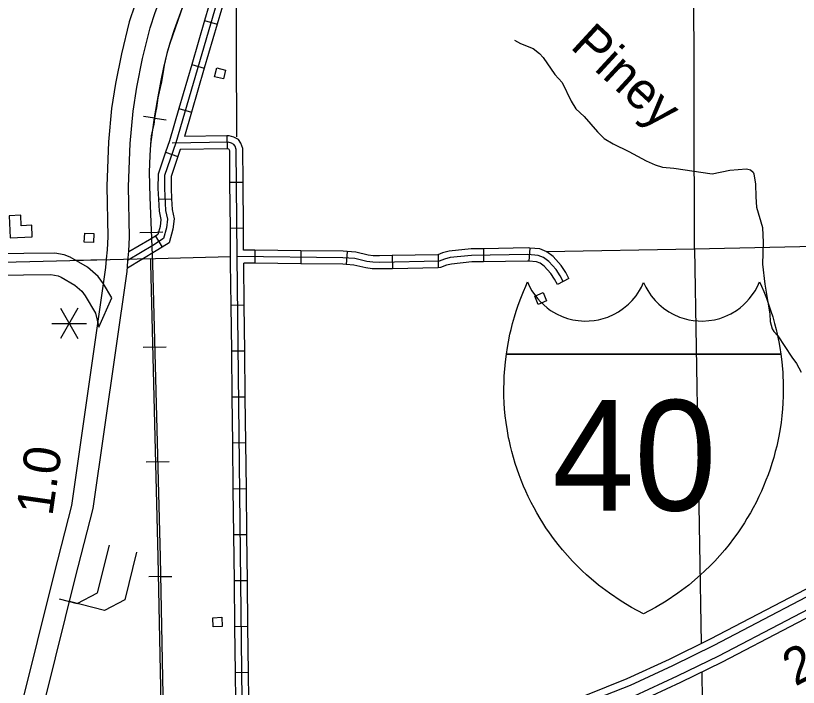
# Model space of a CAD drawing. Extents: x 1084508 to 1142749, y 1057638 to 1093403.
# Drawn here: x 1101971 to 1104795, y 1077367 to 1079791 of the extents above; entities that cross this region are included whole.
import ezdxf

# ---------------------------------------------------------------- set-up
doc = ezdxf.new("R2010")
doc.units = 0
for name, color, linetype in [('Level 10', 7, 'Continuous'), ('Level 15', 7, 'Continuous'), ('Level 19', 7, 'Continuous'), ('Level 23', 7, 'Continuous'), ('Level 31', 7, 'Continuous'), ('Level 32', 7, 'Continuous'), ('Level 33', 7, 'Continuous'), ('Level 35', 7, 'Continuous'), ('Level 40', 7, 'Continuous'), ('Level 48', 7, 'Continuous'), ('Level 5', 7, 'Continuous'), ('Level 56', 7, 'Continuous'), ('Level 58', 7, 'Continuous'), ('Level 6', 7, 'Continuous')]:
    doc.layers.add(name, color=color, linetype=linetype)

msp = doc.modelspace()

# ---------------------------------------------------------------- linework, layer by layer
at = {"layer": 'Level 10'}
msp.add_line((1102270.9, 1078666.9), (1102318, 1078772.6), dxfattribs=at)
for points in [[(1102112.4, 1078934.1), (1101108.6, 1078923.4), (1100079.5, 1078908)], [(1102318, 1078772.6), (1102287.3, 1078823.3), (1102268.6, 1078850.4), (1102230.2, 1078883.4), (1102167.9, 1078919.3), (1102145.2, 1078927.7), (1102112.4, 1078934.1)], [(1100079.8, 1078829.5), (1101109.7, 1078845), (1102097.5, 1078857.1)], [(1102097.5, 1078857.1), (1102123.9, 1078851.9), (1102134.4, 1078848), (1102184.6, 1078819.1), (1102209.7, 1078797.5), (1102221.4, 1078780.6), (1102259.3, 1078718.1), (1102270.9, 1078666.9)]]:
    msp.add_lwpolyline(points, dxfattribs=at)
at = {"layer": 'Level 15'}
for points in [[(1102601.4, 1080345.6), (1102466.9, 1080003.8), (1102400.3, 1079828.9), (1102380.8, 1079769.2), (1102352.2, 1079653.7), (1102330.4, 1079546.7), (1102316.8, 1079455.7), (1102305.9, 1079335.4), (1102299.9, 1079175.8), (1102303.2, 1078993.1), (1102301.2, 1078946.7), (1102297.8, 1078912.2), (1102295.4, 1078882)], [(1102372.7, 1078868.2), (1102376, 1078904.9), (1102379.5, 1078941.3), (1102381.7, 1078992.1), (1102378.4, 1079175.1), (1102384.2, 1079330.4), (1102394.7, 1079446.4), (1102407.7, 1079533.1), (1102428.7, 1079636.5), (1102456.3, 1079747.5), (1102474.3, 1079802.7), (1102540.1, 1079975.5), (1102673.6, 1080315)], [(1102295.4, 1078882), (1102172.2, 1078023.5)], [(1102250.3, 1078012.2), (1102372.7, 1078868.2)], [(1102172.2, 1078023.5), (1102109.9, 1077779.1), (1101926.1, 1077039.1)], [(1102008.9, 1077046.6), (1102186, 1077760), (1102250.3, 1078012.2)]]:
    msp.add_lwpolyline(points, dxfattribs=at)
at = {"layer": 'Level 19'}
for points in [[(1102041.9, 1077000.5), (1102364, 1077029.2), (1102895.3, 1077072.8), (1103063.6, 1077095.3), (1103199.5, 1077115.4), (1103324.5, 1077139.6), (1103502.7, 1077178.6), (1103618.3, 1077206.1), (1103787.8, 1077254.8), (1103877.7, 1077284.5), (1104027.7, 1077339.3), (1104176.7, 1077398.9), (1104329.2, 1077469.3), (1104477.2, 1077541.6), (1104964.7, 1077796.3), (1105121.2, 1077875.3), (1105222.4, 1077921.4), (1105310.5, 1077958), (1105422.2, 1078000.9), (1105533.8, 1078039.7), (1105697.7, 1078089.4), (1105898.8, 1078144), (1106079.8, 1078187.8)], [(1106080.5, 1078160.5), (1105905.5, 1078118.2), (1105705, 1078063.7), (1105542, 1078014.4), (1105431.3, 1077975.8), (1105320.4, 1077933.2), (1105233, 1077897), (1105132.8, 1077851.2), (1104976.9, 1077772.6), (1104489.2, 1077517.7), (1104340.7, 1077445.2), (1104187.3, 1077374.3), (1104037.2, 1077314.4), (1103886.5, 1077259.3), (1103795.7, 1077229.3), (1103625.1, 1077180.3), (1103508.6, 1077152.6), (1103329.9, 1077113.5), (1103204, 1077089.1), (1103067.3, 1077068.8), (1102898.2, 1077046.2), (1102366.3, 1077002.6), (1102029.6, 1076972.6)], [(1102029, 1076931.6), (1102370.2, 1076962), (1102902.9, 1077005.6), (1103073.4, 1077028.4), (1103211.2, 1077048.8), (1103338.5, 1077073.5), (1103518.1, 1077112.8), (1103635.8, 1077140.8), (1103808.1, 1077190.3), (1103900.2, 1077220.8), (1104052.2, 1077276.3), (1104203.8, 1077336.8), (1104358.6, 1077408.3), (1104508, 1077481.3), (1104995.9, 1077736.3), (1105150.8, 1077814.5), (1105249.7, 1077859.5), (1105335.9, 1077895.3), (1105445.7, 1077937.5), (1105555, 1077975.6), (1105716.7, 1078024.5), (1105916, 1078078.6), (1106081.9, 1078118.8)], [(1106082.7, 1078091.5), (1105922.6, 1078052.8), (1105724, 1077998.8), (1105563.3, 1077950.2), (1105454.9, 1077912.4), (1105345.8, 1077870.5), (1105260.3, 1077835.1), (1105162.3, 1077790.4), (1105008.1, 1077712.5), (1104520, 1077457.5), (1104370, 1077384.2), (1104214.3, 1077312.3), (1104061.7, 1077251.3), (1103909, 1077195.6), (1103816, 1077164.8), (1103642.6, 1077115), (1103524.1, 1077086.8), (1103343.9, 1077047.4), (1103215.7, 1077022.5), (1103077.1, 1077002), (1102905.8, 1076979.1), (1102372.4, 1076935.4), (1102017, 1076903.7)]]:
    msp.add_lwpolyline(points, dxfattribs=at)
at = {"layer": 'Level 23'}
for points in [[(1103741.3, 1078569.7), (1103744.9, 1078593.4), (1103748.7, 1078614.3), (1103754.2, 1078641.3), (1103758.3, 1078658.9), (1103763.6, 1078679.7), (1103770.5, 1078704.3), (1103776.8, 1078724.8), (1103783.9, 1078745.9), (1103793.3, 1078771.9), (1103803, 1078796.2), (1103811.1, 1078815.2), (1103817.8, 1078830.1), (1103825.1, 1078814), (1103833.6, 1078798.7), (1103842.8, 1078784.6), (1103854.8, 1078769), (1103864.4, 1078758.5), (1103876.1, 1078747.1), (1103888, 1078737.1), (1103901, 1078727.7), (1103921.5, 1078715.4), (1103942.6, 1078705.6), (1103961.6, 1078698.9), (1103980.5, 1078694), (1104000.7, 1078690.7), (1104024.2, 1078689.1), (1104039.7, 1078689.4), (1104057.4, 1078691.1), (1104073.2, 1078693.8), (1104090.1, 1078697.9), (1104107.1, 1078703.6), (1104130, 1078713.7), (1104145.8, 1078722.5), (1104164.2, 1078735.1), (1104181.8, 1078749.9), (1104194.6, 1078762.8), (1104209.3, 1078780.7), (1104221.4, 1078798.8), (1104228.5, 1078811.5), (1104236.3, 1078828.2)], [(1104236.3, 1078828.2), (1104244.1, 1078811.5), (1104251.2, 1078798.8), (1104263.3, 1078780.7), (1104278, 1078762.8), (1104290.8, 1078749.9), (1104308.4, 1078735.1), (1104326.8, 1078722.5), (1104342.6, 1078713.7), (1104365.5, 1078703.6), (1104382.5, 1078697.9), (1104399.4, 1078693.8), (1104415.2, 1078691.1), (1104432.9, 1078689.4), (1104448.4, 1078689.1), (1104471.9, 1078690.7), (1104492.1, 1078694), (1104510.9, 1078698.9), (1104530, 1078705.6), (1104551.1, 1078715.4), (1104571.6, 1078727.7), (1104584.6, 1078737.1), (1104596.5, 1078747.1), (1104608.2, 1078758.5), (1104617.7, 1078769), (1104629.8, 1078784.6), (1104639, 1078798.7), (1104647.5, 1078814), (1104654.8, 1078830.1), (1104661.5, 1078815.2), (1104669.6, 1078796.2), (1104679.3, 1078771.9), (1104688.7, 1078745.9), (1104695.8, 1078724.8), (1104702.1, 1078704.3), (1104709, 1078679.7), (1104714.3, 1078658.9), (1104718.4, 1078641.3), (1104723.9, 1078614.3), (1104727.7, 1078593.4), (1104731.3, 1078569.7)], [(1104236.3, 1077631.9), (1104192.9, 1077655.1), (1104154.8, 1077678), (1104112.8, 1077706.4), (1104073.6, 1077736.1), (1104030.7, 1077772.6), (1104014.8, 1077787.5), (1103996.6, 1077805.3), (1103979.7, 1077822.7), (1103961.3, 1077842.9), (1103943.2, 1077863.9), (1103928.1, 1077882.6), (1103911.7, 1077903.9), (1103896.8, 1077924.5), (1103883.9, 1077943.4), (1103872.6, 1077960.9), (1103863.2, 1077976), (1103850.8, 1077997.1), (1103841.2, 1078014.4), (1103830.6, 1078034.6), (1103820.3, 1078055.6), (1103811.4, 1078074.9), (1103803.2, 1078093.6), (1103794.7, 1078114.6), (1103787.3, 1078134), (1103780.1, 1078154.3), (1103773.2, 1078175.5), (1103766.7, 1078197.2), (1103761, 1078217.9), (1103756.1, 1078237.6), (1103752.1, 1078255.1), (1103749.4, 1078268.1), (1103744.7, 1078293.3), (1103740.1, 1078322.4), (1103737.1, 1078346.7), (1103734.8, 1078372.2), (1103733.5, 1078392.9), (1103732.6, 1078419.1), (1103732.3, 1078443.6), (1103732.8, 1078470.8), (1103733.5, 1078488.8), (1103734.6, 1078505.2), (1103735.3, 1078515.6), (1103737.9, 1078542.3), (1103741.3, 1078569.7)], [(1104731.3, 1078569.7), (1103741.3, 1078569.7)], [(1103741.3, 1078569.7), (1104731.3, 1078569.7)], [(1104731.3, 1078569.7), (1104734.7, 1078542.3), (1104737.3, 1078515.6), (1104738.1, 1078505.2), (1104739, 1078488.8), (1104739.8, 1078470.8), (1104740.3, 1078443.6), (1104740, 1078419.1), (1104739.1, 1078392.9), (1104737.8, 1078372.2), (1104735.5, 1078346.7), (1104732.5, 1078322.4), (1104727.9, 1078293.3), (1104723.2, 1078268.1), (1104720.5, 1078255.1), (1104716.5, 1078237.6), (1104711.6, 1078217.9), (1104705.9, 1078197.2), (1104699.4, 1078175.5), (1104692.5, 1078154.3), (1104685.3, 1078134), (1104677.9, 1078114.6), (1104669.4, 1078093.6), (1104661.3, 1078074.9), (1104652.3, 1078055.6), (1104642, 1078034.6), (1104631.4, 1078014.4), (1104621.8, 1077997.1), (1104609.4, 1077976), (1104600, 1077960.9), (1104588.7, 1077943.4), (1104575.8, 1077924.5), (1104560.9, 1077903.9), (1104544.6, 1077882.6), (1104529.4, 1077863.9), (1104511.3, 1077842.9), (1104492.9, 1077822.7), (1104476, 1077805.3), (1104457.8, 1077787.5), (1104441.8, 1077772.6), (1104399, 1077736.1), (1104359.8, 1077706.4), (1104317.8, 1077678), (1104279.7, 1077655.1), (1104236.3, 1077631.9)]]:
    msp.add_lwpolyline(points, dxfattribs=at)
at = {"layer": 'Level 31'}
msp.add_lwpolyline([(1102407.2, 1077854.7), (1102364.7, 1077683.1), (1102290.9, 1077643.9), (1102165.4, 1077676.9)], dxfattribs=at)
at = {"layer": 'Level 32'}
for p, q in [((1102652.6, 1079774.3), (1102697.8, 1079761.2)), ((1102606.2, 1079615.3), (1102651.4, 1079602.1)), ((1102559.8, 1079456.2), (1102604.9, 1079443)), ((1102732.6, 1079357.8), (1102733.3, 1079310.7)), ((1102511.8, 1079298.7), (1102556.3, 1079283.5)), ((1102791, 1079189.6), (1102743.9, 1079189.1)), ((1102486, 1079128.6), (1102533.1, 1079130.8)), ((1102792.4, 1079023.8), (1102745.3, 1079023.4)), ((1102474.7, 1078995.9), (1102499.6, 1078956)), ((1102834.2, 1078944.9), (1102833.7, 1078897.9)), ((1103000, 1078943), (1102999.4, 1078896)), ((1103167.1, 1078940.3), (1103163.7, 1078893.3)), ((1103658.1, 1078950.1), (1103658.9, 1078903.1)), ((1103826.1, 1078952.3), (1103822.3, 1078905.4)), ((1103329.1, 1078925.2), (1103330.1, 1078878.1)), ((1103494.7, 1078928.7), (1103495.7, 1078881.6)), ((1103966.7, 1078843.1), (1103925.1, 1078820.9)), ((1102795.3, 1078746.2), (1102748.2, 1078745.6)), ((1102797.2, 1078580.5), (1102750.1, 1078579.9)), ((1102799.1, 1078414.7), (1102752.1, 1078414.2)), ((1102801, 1078249), (1102754, 1078248.5)), ((1102803, 1078083.3), (1102755.9, 1078082.8)), ((1102804.9, 1077917.6), (1102757.8, 1077917)), ((1102806.8, 1077751.9), (1102759.7, 1077751.3)), ((1102808.7, 1077586.1), (1102761.6, 1077585.6)), ((1102810.6, 1077420.4), (1102763.5, 1077419.9))]:
    msp.add_line(p, q, dxfattribs=at)
for points in [[(1102829.7, 1080297.1), (1102548.2, 1079332.5), (1102508, 1079214.8), (1102507.8, 1079168.1), (1102511.5, 1079088.5), (1102518.5, 1079056.9), (1102515, 1079025.4), (1102504.5, 1078986.8), (1102465.5, 1078962.4), (1102376.4, 1078909.2)], [(1102699.1, 1079933.4), (1102652.6, 1079774.3)], [(1102744.3, 1079920.2), (1102697.8, 1079761.2)], [(1102652.6, 1079774.3), (1102606.2, 1079615.3)], [(1102697.8, 1079761.2), (1102651.4, 1079602.1)], [(1102606.2, 1079615.3), (1102559.8, 1079456.2)], [(1102651.4, 1079602.1), (1102604.9, 1079443)], [(1102559.8, 1079456.2), (1102525.7, 1079339.6), (1102511.8, 1079298.7)], [(1102604.9, 1079443), (1102579.5, 1079355.7)], [(1102732.6, 1079357.8), (1102579.5, 1079355.7)], [(1102791, 1079189.6), (1102789.9, 1079312.3), (1102783.3, 1079330.9), (1102774.4, 1079344.2), (1102757.8, 1079353.3), (1102740.8, 1079357.9), (1102732.6, 1079357.8)], [(1103945.9, 1078832), (1103935.3, 1078852), (1103920.3, 1078875.6), (1103893.9, 1078904.6), (1103875.3, 1078918.3), (1103856.1, 1078926.2), (1103818.8, 1078929.3), (1103615, 1078925.9), (1103538.9, 1078918.1), (1103518.4, 1078912.7), (1103498.9, 1078905.3), (1103283, 1078900.6), (1103259, 1078901.5), (1103238.1, 1078904), (1103194.9, 1078914.7), (1103151.6, 1078917.8), (1102769.7, 1078922.1), (1102766.4, 1079308.2), (1102762.1, 1079320.2), (1102758, 1079326.4), (1102749, 1079331.3), (1102737.8, 1079334.3), (1102535.3, 1079331.5)], [(1102564.8, 1079308.4), (1102556.3, 1079283.5)], [(1102733.3, 1079310.7), (1102564.8, 1079308.4)], [(1102743.9, 1079189.1), (1102742.9, 1079304), (1102741.2, 1079308.7), (1102740.2, 1079309.3), (1102734.9, 1079310.7), (1102733.3, 1079310.7)], [(1102511.8, 1079298.7), (1102484.4, 1079218.7), (1102484.2, 1079167.6), (1102486, 1079128.6)], [(1102556.3, 1079283.5), (1102531.5, 1079210.8), (1102531.3, 1079168.6), (1102533.1, 1079130.8)], [(1102745.3, 1079023.4), (1102743.9, 1079189.1)], [(1102792.4, 1079023.8), (1102791, 1079189.6)], [(1102533.1, 1079130.8), (1102534.9, 1079091.6), (1102542.3, 1079058.2), (1102538.2, 1079020.9), (1102524.7, 1078971.7), (1102499.6, 1078956)], [(1102486, 1079128.6), (1102488, 1079085.4), (1102494.7, 1079055.6), (1102491.8, 1079029.8), (1102484.2, 1079001.9), (1102474.7, 1078995.9)], [(1102746.4, 1078898.9), (1102745.3, 1079023.4)], [(1102834.2, 1078944.9), (1102793.1, 1078945.4), (1102792.4, 1079023.8)], [(1102474.7, 1078995.9), (1102453.2, 1078982.5), (1102379.4, 1078938.5)], [(1102499.6, 1078956), (1102477.8, 1078942.3), (1102373.8, 1078880.3)], [(1103000, 1078943), (1102834.2, 1078944.9)], [(1103167.1, 1078940.3), (1103152.6, 1078941.3), (1103000, 1078943)], [(1103329.1, 1078925.2), (1103283.1, 1078924.2), (1103260.8, 1078925), (1103242.4, 1078927.2), (1103198.5, 1078938), (1103167.1, 1078940.3)], [(1103658.1, 1078950.1), (1103613.6, 1078949.4), (1103534.8, 1078941.3), (1103511.2, 1078935.2), (1103494.3, 1078928.7), (1103494.7, 1078928.7)], [(1103826.1, 1078952.3), (1103819.6, 1078952.9), (1103658.1, 1078950.1)], [(1103966.7, 1078843.1), (1103955.6, 1078863.8), (1103939.1, 1078889.9), (1103909.7, 1078922.2), (1103886.9, 1078938.9), (1103861.7, 1078949.4), (1103826.1, 1078952.3)], [(1102797.7, 1077255.1), (1102788.2, 1077320.6), (1102769.7, 1078922.1)], [(1103494.7, 1078928.7), (1103329.1, 1078925.2)], [(1103822.3, 1078905.4), (1103818, 1078905.7), (1103658.9, 1078903.1)], [(1103925.1, 1078820.9), (1103914.9, 1078840.1), (1103901.6, 1078861.2), (1103878, 1078887), (1103863.7, 1078897.6), (1103850.5, 1078903.1), (1103822.3, 1078905.4)], [(1102748.2, 1078745.6), (1102746.4, 1078898.9)], [(1102795.3, 1078746.2), (1102793.6, 1078898.3)], [(1102833.7, 1078897.9), (1102793.6, 1078898.3)], [(1102999.4, 1078896), (1102833.7, 1078897.9)], [(1103163.7, 1078893.3), (1103150.6, 1078894.2), (1102999.4, 1078896)], [(1103330.1, 1078878.1), (1103282.8, 1078877.1), (1103257.2, 1078878), (1103233.9, 1078880.8), (1103191.2, 1078891.3), (1103163.7, 1078893.3)], [(1103495.7, 1078881.6), (1103330.1, 1078878.1)], [(1103658.9, 1078903.1), (1103616.5, 1078902.4), (1103543.1, 1078894.8), (1103525.6, 1078890.3), (1103503.5, 1078881.8), (1103495.7, 1078881.6)], [(1102750.1, 1078579.9), (1102748.2, 1078745.6)], [(1102797.2, 1078580.5), (1102795.3, 1078746.2)], [(1102752.1, 1078414.2), (1102750.1, 1078579.9)], [(1102799.1, 1078414.7), (1102797.2, 1078580.5)], [(1102754, 1078248.5), (1102752.1, 1078414.2)], [(1102801, 1078249), (1102799.1, 1078414.7)], [(1102755.9, 1078082.8), (1102754, 1078248.5)], [(1102803, 1078083.3), (1102801, 1078249)], [(1102757.8, 1077917), (1102755.9, 1078082.8)], [(1102804.9, 1077917.6), (1102803, 1078083.3)], [(1102759.7, 1077751.3), (1102757.8, 1077917)], [(1102806.8, 1077751.9), (1102804.9, 1077917.6)], [(1102761.6, 1077585.6), (1102759.7, 1077751.3)], [(1102808.7, 1077586.1), (1102806.8, 1077751.9)], [(1102763.5, 1077419.9), (1102761.6, 1077585.6)], [(1102810.6, 1077420.4), (1102808.7, 1077586.1)], [(1102774, 1077254.6), (1102764.7, 1077318.8), (1102763.5, 1077419.9)], [(1102821.4, 1077255.7), (1102811.7, 1077322.5), (1102810.6, 1077420.4)]]:
    msp.add_lwpolyline(points, dxfattribs=at)
at = {"layer": 'Level 33'}
msp.add_lwpolyline([(1102127.4, 1077686.7), (1102192.8, 1077669.5), (1102266.5, 1077708.7), (1102309.1, 1077880.4)], dxfattribs=at)
at = {"layer": 'Level 35'}
msp.add_lwpolyline([(1103770.5, 1079702.3), (1103791.8, 1079691.3), (1103837.9, 1079673.2), (1103861.1, 1079655), (1103874.4, 1079639.9), (1103916.2, 1079578.4), (1103942.3, 1079550.6), (1103975.3, 1079482.2), (1103991.3, 1079455.2), (1104021.8, 1079427.2), (1104070.6, 1079372.4), (1104094.6, 1079347.9), (1104126, 1079329.2), (1104183.3, 1079301.5), (1104245.3, 1079267.1), (1104278, 1079253.1), (1104305.1, 1079244.9), (1104345.9, 1079241.4), (1104484, 1079220.8), (1104547.6, 1079233.7), (1104608.1, 1079238), (1104622.1, 1079234.8), (1104631.6, 1079226.4), (1104634.4, 1079219.9), (1104639.9, 1079182.7), (1104641, 1079137.4), (1104643.6, 1079100.3), (1104664.9, 1079027.3), (1104667.7, 1078972.3), (1104665.5, 1078894.4), (1104673.2, 1078822.3), (1104691.7, 1078713.5), (1104693.5, 1078688), (1104700, 1078660.9), (1104705.8, 1078651.4), (1104720.4, 1078635.4), (1104770.8, 1078558.2), (1104788.5, 1078536), (1104805, 1078505)], dxfattribs=at)
at = {"layer": 'Level 40'}
for p, q in [((1102472.4, 1079421.9), (1102431.4, 1079427.9)), ((1102472.4, 1079421.9), (1102513.3, 1079415.8)), ((1102460.5, 1079009.2), (1102419.1, 1079007.6)), ((1102460.5, 1079009.2), (1102501.9, 1079010.9)), ((1102472.6, 1078595.1), (1102431.2, 1078594.1)), ((1102472.6, 1078595.1), (1102514, 1078596.1)), ((1102483, 1078180.9), (1102441.6, 1078179.9)), ((1102483, 1078180.9), (1102524.4, 1078182)), ((1102493, 1077766.7), (1102451.6, 1077765.9)), ((1102493, 1077766.7), (1102534.4, 1077767.5))]:
    msp.add_line(p, q, dxfattribs=at)
for points in [[(1103293.5, 1081677.2), (1102955.6, 1080814.4), (1102738.3, 1080275.5), (1102649.2, 1080027.1), (1102609.7, 1079932.7), (1102575.1, 1079829.4), (1102527.5, 1079690.5), (1102516.6, 1079655.1), (1102504.7, 1079604.4), (1102494.7, 1079557.5), (1102480.8, 1079485.3), (1102470.5, 1079422), (1102462.9, 1079371.3), (1102457.5, 1079325.9), (1102454.3, 1079287), (1102452.3, 1079226.7), (1102455.4, 1079136.8), (1102465, 1078896.6), (1102491.7, 1077837.5), (1102504.8, 1077152.1)], [(1102575.1, 1079829.4), (1102542.6, 1079740.7), (1102526.8, 1079692.4), (1102516.6, 1079655.1), (1102507.1, 1079613.1), (1102502.3, 1079580.8), (1102497, 1079552.2), (1102487.9, 1079516.8), (1102484.2, 1079494.6), (1102478.3, 1079458.8), (1102475.3, 1079441.6), (1102472.1, 1079420.4), (1102469.7, 1079398.5), (1102463.2, 1079374), (1102460.2, 1079357.2), (1102457.5, 1079325.9), (1102454.3, 1079287), (1102452.3, 1079226.7), (1102455.4, 1079136.8), (1102465, 1078896.6), (1102491.7, 1077837.5), (1102504.8, 1077152.1)]]:
    msp.add_lwpolyline(points, dxfattribs=at)
at = {"layer": 'Level 48'}
for p, q in [((1102195.2, 1078735.1), (1102132.5, 1078626.4)), ((1102132.5, 1078735.1), (1102195.2, 1078626.4)), ((1102101.1, 1078680.7), (1102226.6, 1078680.7))]:
    msp.add_line(p, q, dxfattribs=at)
at = {"layer": 'Level 5'}
for points in [[(1104419.8, 1078949.2), (1104415.8, 1080521.5)], [(1102765.2, 1079992.1), (1102767.9, 1079354)], [(1103884.9, 1078940.4), (1104419.8, 1078949.2), (1106051.2, 1078985.3)], [(1104419.8, 1078949.2), (1104444.2, 1077525.5)], [(1102187, 1078908.3), (1102297.7, 1078910.9)], [(1102430.4, 1078914.1), (1102746.2, 1078921.6)], [(1104446, 1077421.3), (1104447.8, 1077318.7)]]:
    msp.add_lwpolyline(points, dxfattribs=at)
at = {"layer": 'Level 56'}
for points in [[(1102720.1, 1079562.9), (1102688.3, 1079570.6), (1102696.1, 1079602.5), (1102727.8, 1079594.7)], [(1102252.4, 1079004.8), (1102251.1, 1078972.2), (1102218.4, 1078973.5), (1102219.7, 1079006.1)], [(1103843.8, 1078779.3), (1103874, 1078791.9), (1103886.5, 1078761.6), (1103856.4, 1078749.1)], [(1102683.5, 1077585.7), (1102682, 1077618.3), (1102714.8, 1077619.8), (1102716.2, 1077587.1)]]:
    msp.add_lwpolyline(points, close=True, dxfattribs=at)
at = {"layer": 'Level 58'}
msp.add_lwpolyline([(1101951, 1078989.2), (1102030.6, 1078992.8), (1102028.8, 1079034.8), (1101991.1, 1079033.1), (1101989.4, 1079070.8), (1101947.4, 1079068.9)], close=True, dxfattribs=at)
at = {"layer": 'Level 6'}
msp.add_lwpolyline([(1100742.6, 1077215.3), (1101131, 1077221.7), (1101109.8, 1078882.6), (1101109.8, 1078892), (1101924.5, 1078902), (1102456.7, 1078914.7), (1102457.2, 1078896.3), (1102483.8, 1077837.3), (1102495.1, 1077249)], dxfattribs=at)

# ---------------------------------------------------------------- texts
at = {"layer": 'Level 23'}
msp.add_text('40', height=398.75, dxfattribs=at).set_placement((1103906.4, 1078005.2))
at = {"layer": 'Level 35'}
msp.add_text('Piney', height=132.58, rotation=317.3553, dxfattribs=at).set_placement((1103967.9, 1079676.7))
at = {"layer": 'Level 48'}
for s, rotation, p in [('1.0', 81.8306, (1102102.9, 1077982.8)), ('2.6', 27.5865, (1104783.4, 1077369.2))]:
    msp.add_text(s, height=132.58, rotation=rotation, dxfattribs=at).set_placement(p)

doc.saveas('drawing.dxf')
